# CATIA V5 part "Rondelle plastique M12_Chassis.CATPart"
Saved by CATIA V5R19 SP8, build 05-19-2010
Part number: Rondelle plastique M12.1
Nomenclature: 106
Material "Plastique": density 1200 kg/m3, Young's modulus 2.2e+09 Pa, Poisson ratio 0.38, thermal expansion 6.84e-05 1/K
Bounding box of the stored display mesh (mm): x 0 to 1, y -10.5 to 10.5, z -10.5 to 10.5
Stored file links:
  C:\Users\rphgr\Desktop\0_Tapis_TC520B_vitesse\Rondelle plastique M12_Chassis.CATPart
  D:\Programmes\DassaultSysteme\win_b64\startup\materials\French\Catalog.CATMaterial
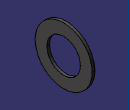
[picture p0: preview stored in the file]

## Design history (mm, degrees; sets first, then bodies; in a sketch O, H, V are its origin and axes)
AxisSystem1: origin (0, 0, 0), X (1, 0, 0), Y (0, 1, 0), Z (0, 0, 1)
Body1 (main body), material "Plastique"
  Sketch1 on YZ plane of AxisSystem1, origin (0, 0, 0), H (0, 1, 0), V (0, 0, 1)
    circle A1 centre (0, 0) radius 6.2
    circle A2 centre (0, 0) radius 10.5
    radius A2 = 10.5
    radius A1 = 6.2
  Pad1: profile Sketch1, direction (1, 0, 0), length 1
